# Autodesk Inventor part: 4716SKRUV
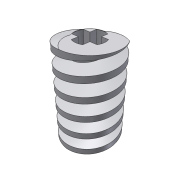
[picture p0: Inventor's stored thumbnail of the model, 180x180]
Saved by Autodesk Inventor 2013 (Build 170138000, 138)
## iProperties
Created: 2013-03
Part Number: 4716SKRUV
Material: Generic
Document SubType Name: Modeling
Designer: perblt
Density: 1 g/cm^3
Translation Standard: STEP AP203
FileName: 4716SKRUV
PreProcessor: PRO/ENGINEER BY PARAMETRIC TECHNOLOGY CORPORATION, 2010370
PostProcessor: Build: 138, Release: 2013 RTM - Date: Thu 03/01/2012
Sent Units: millimeter
Uncertainty: 0.003062826453867
Author: perblt
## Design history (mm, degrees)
node "4716SKRUV1"
node "4716SKRUV"
node "Base1"
